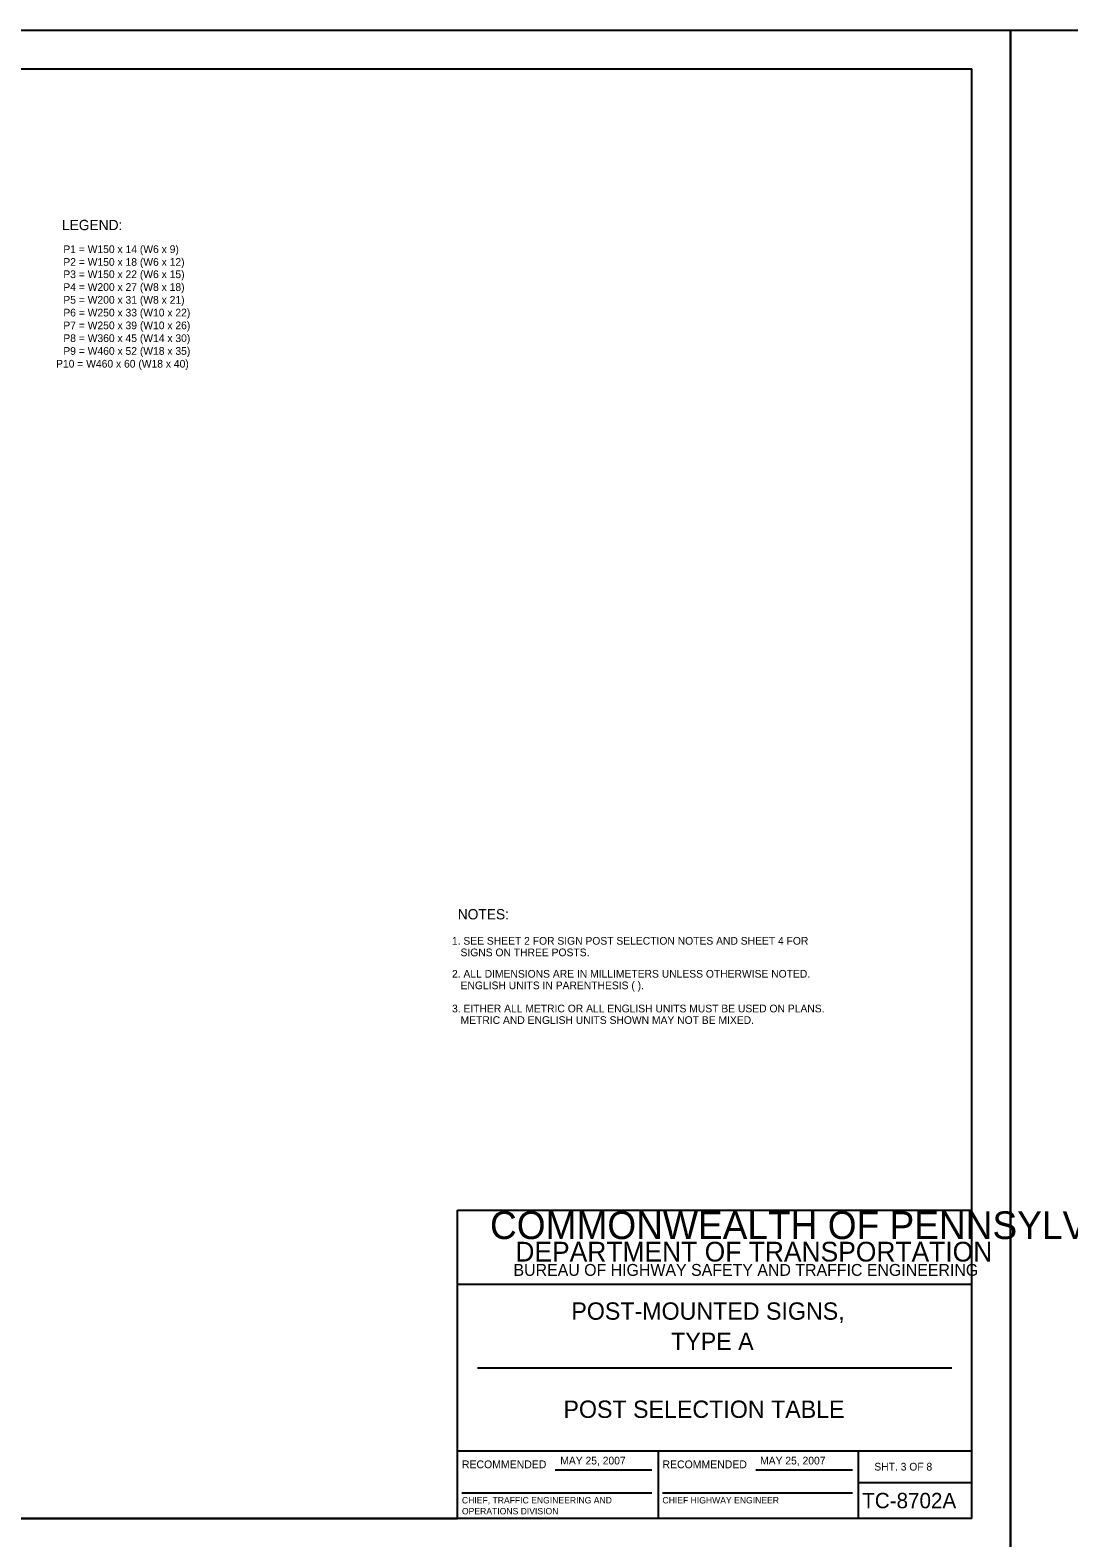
# Model space of a CAD drawing. Extents: x 637580 to 641008, y 294594 to 295782.
# Drawn here: x 639722 to 640126, y 295195 to 295782 of the extents above; entities that cross this region are included whole.
import ezdxf

# ---------------------------------------------------------------- set-up
doc = ezdxf.new("R2010")
doc.units = 0
for name, color, linetype in [('1', 7, 'Continuous'), ('2', 7, 'Continuous'), ('PLT-BNDY', 7, 'Continuous')]:
    doc.layers.add(name, color=color, linetype=linetype)

msp = doc.modelspace()

# ---------------------------------------------------------------- linework, layer by layer
at = {"layer": '1'}
for p, q in [((639302.31, 295766.63), (640088.31, 295766.63)), ((640088.31, 295202.63), (640088.31, 295766.63)), ((639888.31, 295202.63), (639888.31, 295322.63)), ((639888.31, 295322.63), (640088.31, 295322.63)), ((640088.31, 295293.63), (639888.31, 295293.63)), ((639896.06, 295261.31), (640080.56, 295261.31)), ((639888.31, 295229), (640088.31, 295229)), ((639966.31, 295229), (639966.31, 295202.63)), ((640044.19, 295202.63), (640044.19, 295229)), ((639926.24, 295221.57), (639963.87, 295221.57)), ((640004.24, 295221.57), (640041.87, 295221.57)), ((640044.19, 295216.63), (640088.31, 295216.63)), ((639889.99, 295212.68), (639963.87, 295212.68)), ((639967.99, 295212.68), (640041.87, 295212.68)), ((640088.31, 295202.63), (639302.31, 295202.63)), ((639302.31, 295202.63), (639888.31, 295202.63))]:
    msp.add_line(p, q, dxfattribs=at)
at = {"layer": 'PLT-BNDY'}
for points in [[(639262.31, 295781.63), (640103.31, 295781.63), (640103.31, 295187.63), (639262.31, 295187.63)], [(640103.31, 295781.63), (640944.31, 295781.63), (640944.31, 295187.63), (640103.31, 295187.63)]]:
    msp.add_lwpolyline(points, close=True, dxfattribs=at)

# ---------------------------------------------------------------- texts
at = {"layer": '1'}
for s, height, p in [('LEGEND:', 4.003, (639734.41, 295703.83)), ('P1 = W150 x 14 (W6 x 9)', 3, (639734.94, 295694.92)), ('P2 = W150 x 18 (W6 x 12)', 3, (639734.94, 295689.95)), ('P3 = W150 x 22 (W6 x 15)', 3, (639734.94, 295685.17)), ('P4 = W200 x 27 (W8 x 18)', 3, (639734.94, 295680.19)), ('P5 = W200 x 31 (W8 x 21)', 3, (639734.94, 295675.22)), ('P6 = W250 x 33 (W10 x 22)', 3, (639734.94, 295670.25)), ('P7 = W250 x 39 (W10 x 26)', 3, (639734.94, 295665.28)), ('P8 = W360 x 45 (W14 x 30)', 3, (639734.94, 295660.3)), ('P9 = W460 x 52 (W18 x 35)', 3, (639734.94, 295655.33)), ('P10 = W460 x 60 (W18 x 40)', 3, (639732.12, 295650.36)), (' 1. SEE SHEET 2 FOR SIGN POST SELECTION NOTES AND SHEET 4 FOR', 3, (639884.97, 295425.87)), ('    SIGNS ON THREE POSTS.', 3, (639884.97, 295421.37)), ('COMMONWEALTH OF PENNSYLVANIA', 10.7828, (639900.9, 295311.36)), ('DEPARTMENT OF TRANSPORTATION', 7.6837, (639910.76, 295302.61)), ('BUREAU OF HIGHWAY SAFETY AND TRAFFIC ENGINEERING', 4.6253, (639910.04, 295297.04)), ('POST-MOUNTED SIGNS,', 6.75, (639932.54, 295279.97)), ('TYPE A', 6.75, (639971.35, 295268.22)), ('POST SELECTION TABLE', 6.75, (639929.47, 295241.78)), ('RECOMMENDED', 3.048, (639889.99, 295222.2)), ('RECOMMENDED', 3.048, (639967.99, 295222.2)), ('SHT. 3 OF 8', 3, (640050.4, 295221.31)), ('CHIEF, TRAFFIC ENGINEERING AND', 2.5, (639889.99, 295208.51)), ('CHIEF HIGHWAY ENGINEER', 2.5, (639967.99, 295208.51)), ('TC-8702A', 6, (640045.68, 295206.63)), ('OPERATIONS DIVISION', 2.5, (639889.99, 295204.26))]:
    msp.add_text(s, height=height, dxfattribs=at).set_placement(p)
at = {"layer": '2'}
for s, height, p in [('NOTES:', 4.003, (639888.35, 295435.71)), (' 2. ALL DIMENSIONS ARE IN MILLIMETERS UNLESS OTHERWISE NOTED.', 3, (639885, 295413.04)), ('    ENGLISH UNITS IN PARENTHESIS ( ).', 3, (639885, 295408.54)), (' 3. EITHER ALL METRIC OR ALL ENGLISH UNITS MUST BE USED ON PLANS.', 3, (639885, 295399.54)), ('    METRIC AND ENGLISH UNITS SHOWN MAY NOT BE MIXED.     ', 3, (639885, 295395.04)), ('MAY 25, 2007', 3, (639928.25, 295223.67)), ('MAY 25, 2007', 3, (640005.97, 295223.67))]:
    msp.add_text(s, height=height, dxfattribs=at).set_placement(p)

doc.saveas('drawing.dxf')
